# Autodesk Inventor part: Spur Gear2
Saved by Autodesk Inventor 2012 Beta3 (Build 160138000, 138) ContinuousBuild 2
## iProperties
Created: 2011-01
Part Number: Spur Gear2
Material: Steel
Document SubType Name: Modeling
Designer: Beta-8540w
Categories: <?xml version="1.0" encoding="UTF-16"?> <MemberInstance><Categories><FamilyTemplate><FamilyTemplateParameter ValueType="xs:double" Id="1" ObjectReferenceKey="da
Density: 1 g/cm^3
CustomPartVersion: 1
Author: Beta-8540w
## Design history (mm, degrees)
sketch "Sketch1"
  geometry: C1 r 40.8 at (0, 0)
  constraints: 1 centre point
  dimensions: "d0" = 81.6 diameter of C1 (= da_da)
extrude "Extrusion1" new body sketch "Sketch1" distance "d1" = 13 (= da_b); taper "d2" = 0 deg
workplane "Work Plane2"
sketch "Sketch2"
  geometry: C1 r 40.8 at (0, 0) reference; C2 r 40 at (0, 0)
  constraints: 1 centre point, 1 coincident
  dimensions: "d3" = 80 diameter of C2 (= da_dw)
feature "Pitch Diameter" sketch "Sketch2" dims "d4" = 10, "d5" = 0
workplane "Work Plane8"
workplane "Work Plane9"
feature "Spur Gear" dims "da_b" = 13, "da_d" = 80, "da_aw" = 50, "da_da" = 81.6, "da_df" = 78, "da_dw" = 80, angle "da_beta" = 0 deg, "da_lefttooth" = 0, "da_righttooth" = 0
body "Solid1"
body "Srf1"
other parameters: "d17" = 0, "d34" = 0.31416 (computed from da_z), "d39" = 0, "d41" = 0, "d47" = 0, "d48" = 0
